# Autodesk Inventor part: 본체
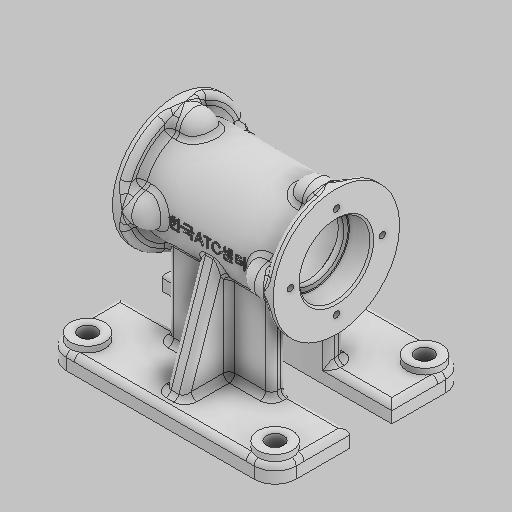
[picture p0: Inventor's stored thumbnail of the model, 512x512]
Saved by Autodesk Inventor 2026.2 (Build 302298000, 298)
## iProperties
Created: 2026-06
Part Number: 본체
Material: 알루미늄 6061
Document SubType Name: Modeling
Designer: sec7
Density: 2.7 g/cm^3
Appearance: 기본값
Mass: 619.66 g
Surface Area: 680.375 cm^2
Volume: 229.504 cm^3
Author: sec7
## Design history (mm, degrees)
sketch "스케치1"
  geometry: L1 (-42, 0)-(42, 0); L2 (-42, 16)-(42, 16); L3 (42, 16)-(42, 0); L4 (-42, 18.5)-(-30.3, 18.5); L5 (-42, 18.5)-(-42, 0); L6 (-30, 18.2)-(-30, 0); L7 (-27, 0)-(-27, 17); L8 (-24, 20)-(24, 20); L9 (27, 17)-(27, 0); L10 (30, 0)-(30, 18.2); L11 (30.3, 18.5)-(42, 18.5); L12 (42, 18.5)-(42, 16); L13 (-42, 18.5)-(-42, 33); L14 (-42, 33)-(-37, 33); L15 (-37, 33)-(-37, 25); L16 (-37, 25)-(37, 25); L17 (37, 25)-(37, 33); L18 (37, 33)-(42, 33); L19 (42, 33)-(42, 18.5); L20 (-37, 29.455)-(-32, 29.455); L21 (-37, 25)-(-24.828, 25); A1 r 0.3 centre (-30.3, 18.2) between (-30, 18.2) and (-30.3, 18.5); A2 r 0.3 centre (30.3, 18.2) between (30.3, 18.5) and (30, 18.2); A3 r 3 centre (-24, 17) between (-24, 20) and (-27, 17); A4 r 3 centre (24, 17) between (27, 17) and (24, 20); A5 r 8 centre (-32, 21.455) between (-24.828, 25) and (-32, 29.455); 13 further points
  constraints: 42 end point, 14 point on line, 12 perpendicular, 10 point on circle, 9 tangent, 5 centre point, 4 vertical, 3 horizontal, 2 coincident, 2 equal radius, 2 midpoint, 1 collinear, 1 vertical alignment
  dimensions: "d1" = 84 distance of L1.start L1.end; "d3" = 32 diameter of L2 L1; "d4" = 37 diameter of L4 L1; "d5" = 40 diameter of L8 L1; "d6" = 54 distance between parallel lines of L9 L7; "d7" = 12 distance between parallel lines of L6 L5; "d8" = 37 diameter of L11 L1; "d9" = 12 distance between parallel lines of L3 L10; "d11" = 66 diameter of L14 L1; "d12" = 66 diameter of L18 L1; "d13" = 50 diameter of L16 L1; "d14" = 5 distance between parallel lines of L15 L13; "d15" = 5 distance between parallel lines of L19 L17; "d17" = 0.3 radius of A1; "d118" = 3 radius of A3; "d119" = 10 distance from line of L20.end L13; "d120" = 8 radius of A5; "d144" = 17.17158 distance from line of L21.end L13
revolve "회전1" sketch "스케치1" stored, may be unused: angle "d16" = 360 deg
node "작업 평면2"
sketch "스케치3"
  geometry: L1 (-60, 50)-(60, 50); L2 (60, 50)-(60, -50); L3 (60, -50)-(-60, -50); L4 (-60, -50)-(-60, 50); L5 (-60, 50)-(60, -50); L6 (60, 50)-(-60, -50); L7 (60, -11)-(-60, -11); L8 (60, 11)-(-60, 11); 1 further point
  constraints: 16 end point, 4 point on line, 3 perpendicular, 2 midpoint, 2 parallel, 1 horizontal
  dimensions: "d26" = 120 distance of L2.end L3.end; "d27" = 100 distance of L1.end L2.end; "d28" = 39 distance between parallel lines of L7 L3; "d29" = 39 distance between parallel lines of L1 L8
extrude "돌출2" join sketch "스케치3" distance "d30" = 9; taper "d31" = 0 deg
sketch "스케치4"
  geometry: L1 (49, -39)-(-49, -39); L2 (-49, -39)-(-49, 39); L3 (-49, 39)-(49, 39); L4 (49, 39)-(49, -39); L5 (49, -39)-(-49, 39); L6 (-49, -39)-(49, 39); C1 r 9 at (-49, 39); C2 r 9 at (49, 39); C3 r 9 at (49, -39); C4 r 9 at (-49, -39); 1 further point
  constraints: 12 end point, 4 centre point, 4 coincident, 2 midpoint, 2 parallel, 1 horizontal, 1 perpendicular
  dimensions: "d32" = 98 distance of L2.end L3.end; "d33" = 78 distance of L1.end L2.end; "d34" = 18 diameter of C1; "d35" = 18 diameter of C2; "d36" = 18 diameter of C3; "d37" = 18 diameter of C4
extrude "돌출3" join sketch "스케치4" distance "d38" = 3; taper "d39" = 0 deg
sketch "스케치5"
  geometry: L1 (0, 0)-(98, 0); L2 (98, 0)-(98, 78); L3 (98, 78)-(0, 78); L4 (0, 78)-(0, 0); C1 r 9 at (0, 0) reference; C2 r 9 at (98, 78) reference; C3 r 4.5 at (0, 0); C4 r 4.5 at (0, 78); C5 r 4.5 at (98, 78); C6 r 4.5 at (98, 0); 1 further point
  constraints: 8 end point, 4 centre point, 4 coincident, 2 parallel, 1 horizontal, 1 perpendicular
  dimensions: "d40" = 9 diameter of C3; "d41" = 9 diameter of C4; "d42" = 9 diameter of C5; "d43" = 9 diameter of C6
extrude "돌출4" cut sketch "스케치5" extent not by distance; stored distance "d44" = 0; taper "d45" = 0 deg
sketch "스케치6"
  geometry: L1 (-60, 11)-(60, 11) reference; L2 (60, -11)-(-60, -11) reference; L3 (-27, -11)-(27, -11); L4 (-27, 11)-(27, 11); L5 (-27, -11)-(-27, -19); L6 (-27, -19)-(27, -19); L7 (27, -19)-(27, -11); L8 (-27, 11)-(-27, 19); L9 (-27, 19)-(27, 19); L10 (27, 19)-(27, 11); 7 further points
  constraints: 16 end point, 4 midpoint, 4 perpendicular, 2 horizontal, 2 vertical
  dimensions: "d46" = 54 distance of L3.start L3.end; "d47" = 54 distance of L4.start L4.end; "d48" = 8 distance of L3.start L5.end; "d49" = 8 distance of L4.start L8.end
extrude "돌출5" join sketch "스케치6" stored distance "d50" = 10; taper "d51" = 0 deg
sketch "스케치7"
  geometry: L1 (-61, 50)-(-61, 11) reference; L2 (-17.454, 28.006)-(-61, 43); L3 (-70, 50)-(-61, 50) reference; L4 (-61, 19)-(-16.248, 19) reference; 2 further points
  constraints: 2 end point, 1 point on line, 2 other
  dimensions: "d52" = 7 distance from line of L2.end L3; "d53" = 19 deg angle of L4 L2
feature "리브1" sketch "스케치7" dims "d54" = 1, "d55" = 10, "d56" = 0, "d57" = 0, "d58" = 1, "d59" = 1
node "작업 평면1"
sketch "스케치2"
  geometry: L1 (25, 0)-(-25, 0); L2 (0, 25)-(0, -25); C1 r 8 at (25, 0); C2 r 8 at (0, 25); C3 r 8 at (-25, 0); C4 r 8 at (0, -25); A1 r 25 centre (0, 0) between (25, 0) and (0, 25) reference; 9 further points
  constraints: 4 centre point, 4 end point, 4 point on circle, 1 horizontal, 1 vertical
  dimensions: "d19" = 16 diameter of C1; "d20" = 16 diameter of C2; "d21" = 16 diameter of C3; "d22" = 16 diameter of C4; "d73" = 50 distance of L1.start L1.end; "d74" = 50 distance of L2.start L2.end
extrude "돌출1" join sketch "스케치2" distance "d23" = 5; taper "d24" = 0 deg
sketch "스케치10"
  geometry: L1 (-3.55, 23.157)-(3.55, 23.157); A1 r 25 centre (0, 0) between (23.72, 7.897) and (7.897, 23.72) reference; A2 r 25 centre (0, 0) between (-7.897, 23.72) and (-23.72, 7.897) reference; A3 r 8 centre (0, 25) between (7.897, 23.72) and (-7.897, 23.72) reference; A4 r 25 centre (0, 0) between (7.897, 23.72) and (-7.897, 23.72); A5 r 4 centre (0, 25) between (-3.55, 23.157) and (3.55, 23.157); 1 further point
  constraints: 4 point on circle, 2 centre point, 2 coincident, 2 end point, 1 horizontal
revolve "회전3" sketch "스케치10" stored, may be unused: angle "d71" = 180 deg
fillet "모깎기1" dims "d72" = 3
fillet "모깎기2" dims "d95" = 3
sketch "스케치13"
  geometry: L1 (-42, 0)-(42, 0); L2 (-42, 16)-(42, 16); L3 (42, 16)-(42, 0); L4 (-42, 18.5)-(-30.3, 18.5); L5 (-42, 18.5)-(-42, 0); L6 (-30, 18.2)-(-30, 0); L7 (-27, 0)-(-27, 17); L8 (-24, 20)-(24, 20); L9 (27, 17)-(27, 0); L10 (30, 0)-(30, 18.2); L11 (30.3, 18.5)-(42, 18.5); L12 (42, 18.5)-(42, 16); L13 (-42, 18.5)-(-42, 33); L14 (-42, 33)-(-37, 33); L15 (-37, 33)-(-37, 25); L16 (-37, 25)-(37, 25); L17 (37, 25)-(37, 33); L18 (37, 33)-(42, 33); L19 (42, 33)-(42, 18.5); A1 r 0.3 centre (-30.3, 18.2) between (-30, 18.2) and (-30.3, 18.5); A2 r 0.3 centre (30.3, 18.2) between (30.3, 18.5) and (30, 18.2); A3 r 3 centre (-24, 17) between (-24, 20) and (-27, 17); A4 r 3 centre (24, 17) between (27, 17) and (24, 20); 21 further points
  constraints: 38 end point, 12 perpendicular, 8 point on circle, 8 point on line, 8 tangent, 4 centre point, 4 coincident, 4 vertical, 2 equal radius, 2 horizontal, 2 midpoint, 1 vertical alignment
  dimensions: "d156" = 84 distance of L1.start L1.end; "d157" = 32 diameter of L2 L1; "d158" = 37 diameter of L4 L1; "d159" = 40 diameter of L8 L1; "d160" = 54 distance between parallel lines of L9 L7; "d161" = 12 distance between parallel lines of L6 L5; "d162" = 37 diameter of L11 L1; "d163" = 12 distance between parallel lines of L3 L10; "d164" = 84 distance from line of L2.start L12; "d165" = 66 diameter of L14 L1; "d166" = 66 diameter of L18 L1; "d167" = 50 diameter of L16 L1; "d168" = 5 distance between parallel lines of L15 L13; "d169" = 5 distance between parallel lines of L19 L17; "d170" = 0.3 radius of A1; "d173" = 3 radius of A3
revolve "회전4" sketch "스케치13" stored, may be unused: angle "d174" = 360 deg
sketch "스케치14"
  geometry: L1 (-70, 50)-(-70, 11) reference; L2 (-70, -11)-(-70, -50) reference; L3 (-70, 11)-(-70, -11); L4 (-70, 0)-(-50, 0); L5 (-61, 11)-(-22.45, 11) reference; L6 (-50, 11)-(-50, -11); L7 (-61, -11)-(-22.45, -11) reference; L8 (-61, 11)-(-22.45, 11) reference; C1 r 33 at (0, 0) reference; 1 further point
  constraints: 6 end point, 2 vertical, 1 horizontal, 1 midpoint, 1 point on line
  dimensions: "d175" = 20 distance of L4.start L4.end
feature "리브2" sketch "스케치14" dims "d176" = 1, "d177" = 10, "d178" = 0, "d179" = 0, "d180" = 1, "d181" = 1
node "작업 평면3"
sketch "스케치15"
  geometry: L1 (-60, -70)-(60, -70) reference; L2 (0, -70)-(0, 0); 1 further point
  constraints: 2 end point, 1 coincident, 1 midpoint, 1 vertical, 1 other
  dimensions: "d183" = 70 distance of L2.start L2.end (derived)
feature "엠보싱1" sketch "스케치15" dims "d1" = 84, "d3" = 32, "d4" = 37, "d5" = 40, "d6" = 54, "d7" = 12, "d8" = 37, "d9" = 12, "d11" = 66, "d12" = 66, "d13" = 50, "d14" = 5, "d15" = 5, "d17" = 0.3, "d118" = 3, "d119" = 10, "d120" = 8, "d144" = 17.17158, "d184" = 0.5, "d185" = 0
sketch "스케치16"
  geometry: L1 (0, 24)-(0, -24); L2 (-24, 0)-(24, 0); A1 r 24 centre (0, 0) between (0, 24) and (0, -24); 5 further points
  constraints: 5 point on circle, 4 coincident, 4 end point, 1 centre point, 1 perpendicular, 1 vertical
  dimensions: "d186" = 48 diameter of A1; "d187" = 48 distance of L2.start L2.end; "d188" = 48 distance of L1.start L1.end; "d189" = 24 distance from line of point (0, 24) L2
hole "구멍2" sketch "스케치16" at (0, 24), (-24, 0), (24, 0), (0, -24) diameter "d190" = 3.242; stored, may be unused: countersink angle "d194" = 90 deg, drill point angle "d196" = 120 deg; dims "d191" = 8, "d192" = 4, "d193" = 2, "d195" = 10
chamfer "모따기1" distance "d197" = 1; stored, may be unused: second distance "d198" = 2, angle "d199" = 45 deg
chamfer "모따기2" distance "d200" = 1; stored, may be unused: second distance "d201" = 2, angle "d202" = 45 deg
fillet "모깎기4" dims "d204" = 3
fillet "모깎기5" dims "d205" = 11
fillet "모깎기6" dims "d206" = 3
fillet "모깎기7" dims "d207" = 3
fillet "모깎기8" dims "d208" = 3
fillet "모깎기9" dims "d209" = 2
fillet "모깎기10" dims "d210" = 3
fillet "모깎기11" dims "d211" = 3
fillet "모깎기12" dims "d212" = 3
fillet "모깎기13" dims "d213" = 3
feature "ى耀ً耀ٍ耀ُ耀ّ耀ٓ耀ٕ耀ٗ耀" dims "d1" = 84, "d3" = 32, "d4" = 37, "d5" = 40, "d6" = 54, "d7" = 12, "d8" = 37, "d9" = 12, "d11" = 66, "d12" = 66, "d13" = 50, "d14" = 5, "d15" = 5, "d16" = 360 deg, "d17" = 0.3, "d18" = -37, "d19" = 16, "d20" = 16, "d21" = 16, "d22" = 16, "d23" = 5, "d24" = 0, "d25" = -70, "d26" = 120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
feature "࠲耀࠴耀࠶耀࠸耀࠺耀࠼耀࠾耀ࡀ耀" dims "d1" = 84, "d3" = 32, "d4" = 37, "d5" = 40, "d6" = 54, "d7" = 12, "d8" = 37, "d9" = 12, "d11" = 66, "d12" = 66, "d13" = 50, "d14" = 5, "d15" = 5, "d16" = 360 deg, "d17" = 0.3, "d18" = -37, "d19" = 16, "d20" = 16, "d21" = 16, "d22" = 16, "d23" = 5, "d24" = 0, "d25" = -70, "d26" = 120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
node "솔리드1"
mirror "미러1"
pattern_circular "원형 패턴1" dims angle "d93" = 360 deg
mirror "미러3"
mirror "미러4"
feature "A9D066F2-1C7D-4E18-AEED-F7BC21143FA4" dims "d190" = 3.242, "d191" = 8, "d192" = 4, "d193" = 2, "d194" = 90 deg, "d195" = 10, "d196" = 120 deg
